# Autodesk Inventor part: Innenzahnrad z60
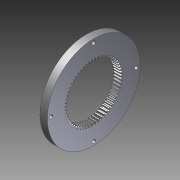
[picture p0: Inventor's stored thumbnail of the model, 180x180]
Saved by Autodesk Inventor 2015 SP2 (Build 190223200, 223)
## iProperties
Created: 2015-08
Part Number: Innenzahnrad z60
Material: Messing, weicher Gelbton
Document SubType Name: Modeling
Designer: rYan
Mass: 41.9941 g
Surface Area: 39.6928 cm^2
Volume: 4.95798 cm^3
Density: 8.47 g/cm^3
Appearance: Messing - satiniert
Title: c:/PPEXPORT/antriebselemente_und_normteile/innenkraenze/artikel_nr___26146000.stp
Creation Date: 2007-11-06
Author: rYan
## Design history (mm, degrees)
node "261460001"
sketch "Skizze1" dims "d0" = 46
  geometry: L1 (-35, 0)-(35, 0) reference; 3 further points
  constraints: 1 coincident, 1 horizontal alignment, 1 point on line, 2 other
hole "Bohrung1" sketch "Skizze1" at (-23, 0) diameter "d1" = 2; stored, may be unused: countersink angle "d5" = 90 deg, drill point angle "d7" = 118 deg; dims "d2" = 6, "d3" = 4, "d4" = 2, "d6" = 8
pattern_circular "Runde Anordnung1" dims angle "d9" = 360 deg
node "1"
node "Basis1"
